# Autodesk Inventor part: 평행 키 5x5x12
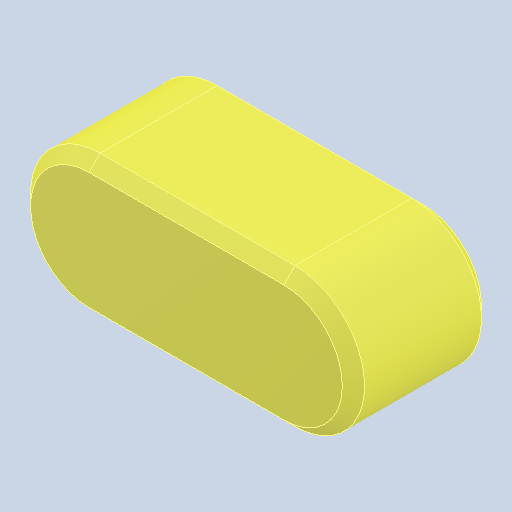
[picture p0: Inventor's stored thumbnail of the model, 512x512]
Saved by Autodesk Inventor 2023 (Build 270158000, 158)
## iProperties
Created: 2025-03
Part Number: 평행 키 5x5x12
Material: 강철, 연강
Description: 키 및 해당 키홈
Document SubType Name: Modeling
Designer: Admin
Density: 7.85 g/cm^3
Appearance: 기본값
Author: jhkim
Sending System: Autodesk Inventor 2025
Preprocessor: ST-DEVELOPER v20
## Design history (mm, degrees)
feature "Solid1"
node "솔리드1"
